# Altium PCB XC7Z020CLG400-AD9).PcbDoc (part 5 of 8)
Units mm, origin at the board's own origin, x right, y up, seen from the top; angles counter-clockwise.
Board outline 38 x 38 mm, 14 copper layers (Top Layer, GND02, ART03, PWR04, ART05, GND06, ART07, ART08, PWR09, ART10, GND11, ART12, PWR13, Bottom Layer); 276 components, 302 nets, 1684 pads, 1576 vias.
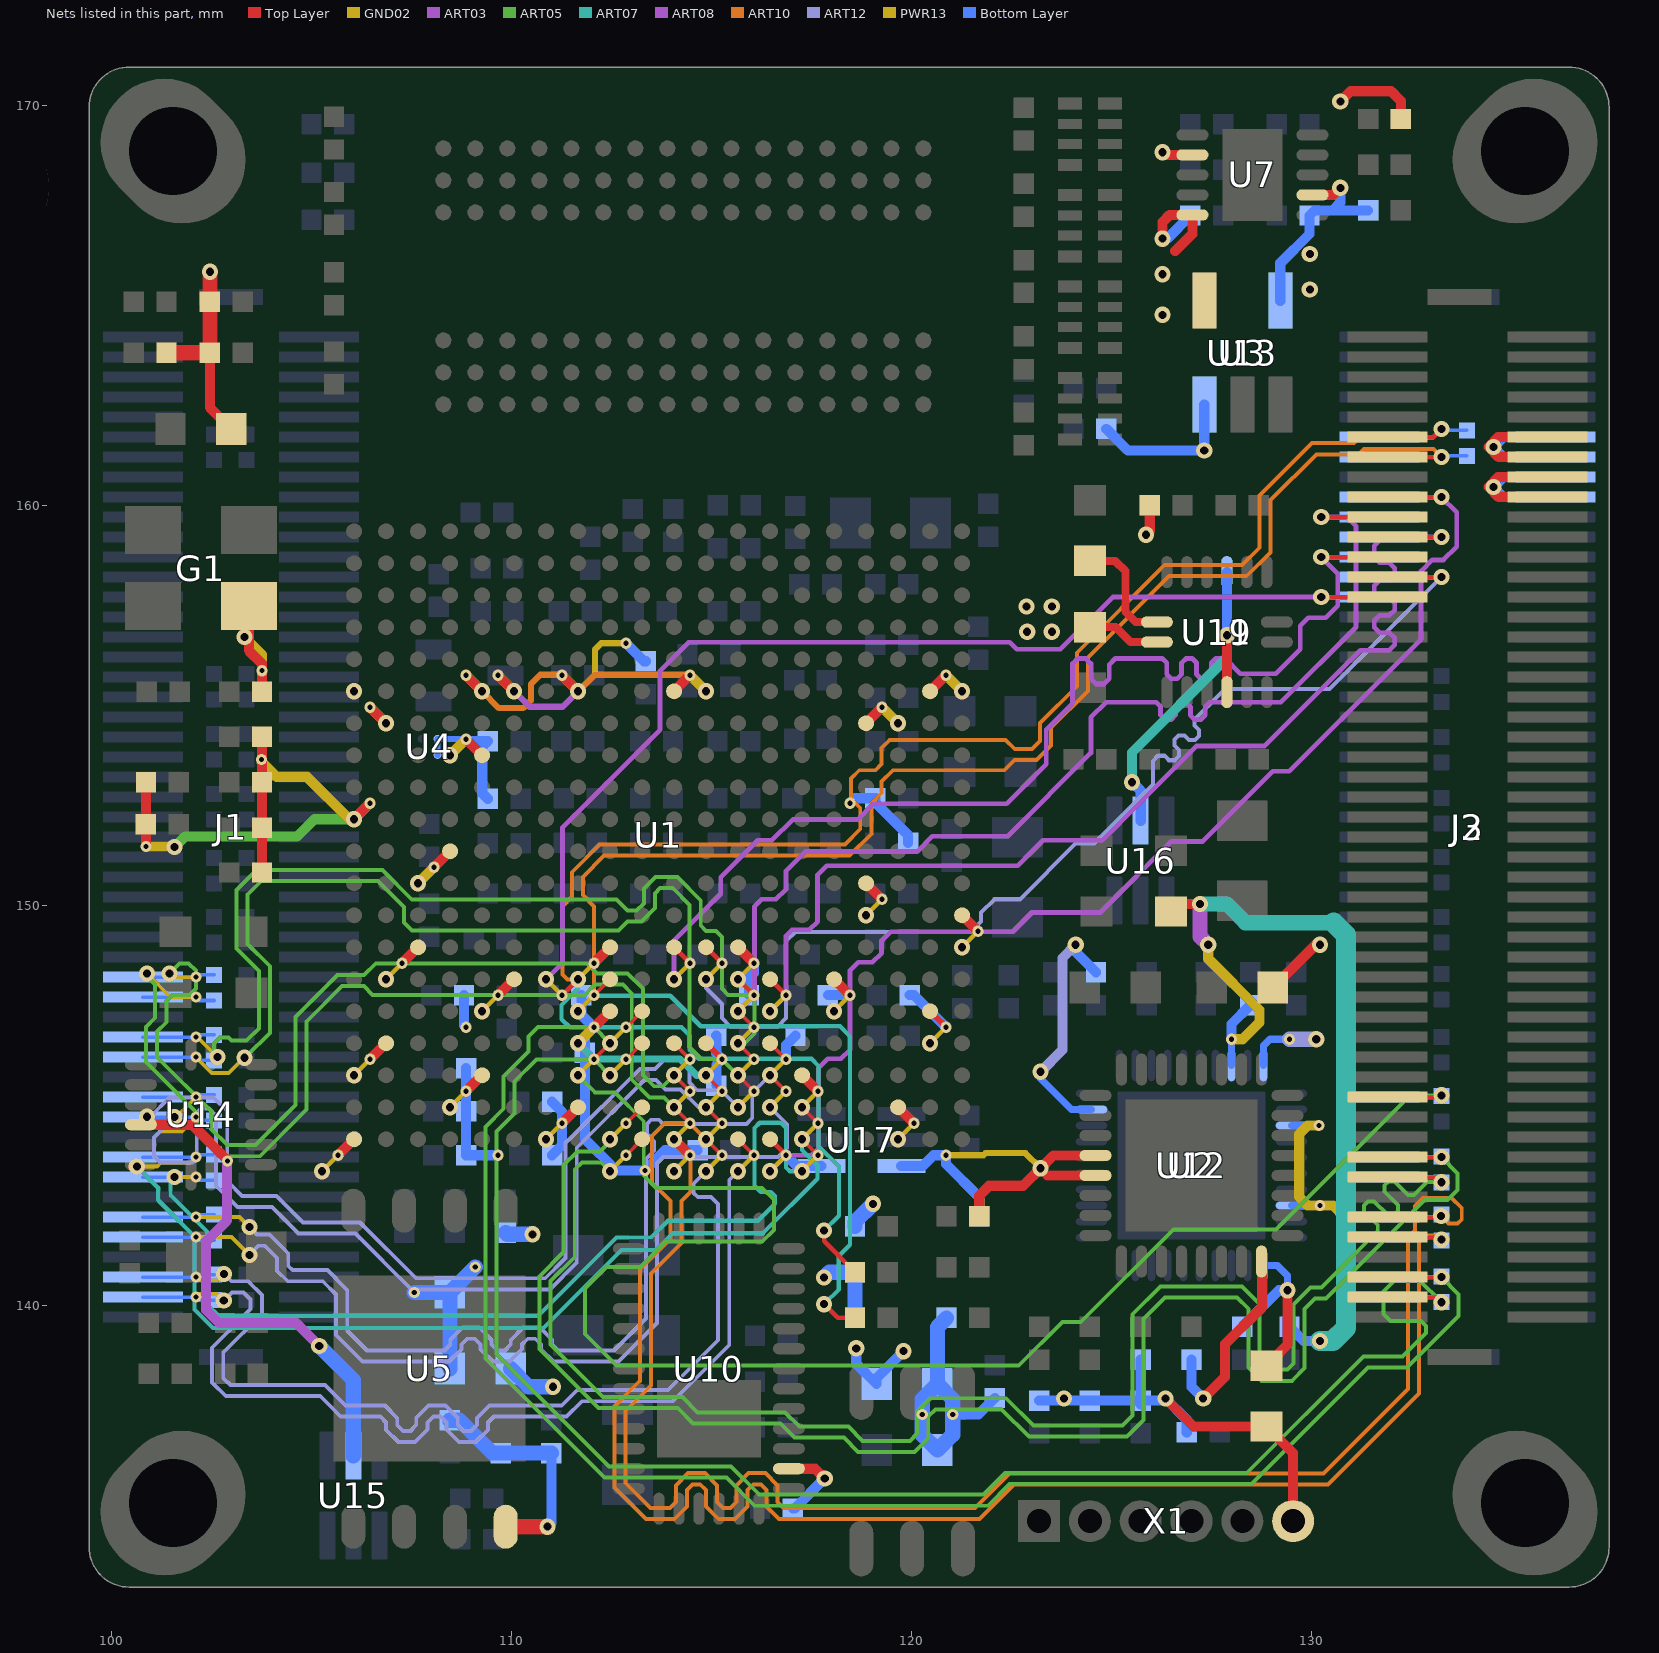
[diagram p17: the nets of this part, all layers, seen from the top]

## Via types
v1: diameter 0.406, hole 0.203, GND02 to PWR13, 466 vias
v2: diameter 0.279, hole 0.127, Top Layer to GND02, tented top, 373 vias
v3: diameter 0.406, hole 0.203, Top Layer to Bottom Layer, 324 vias
v4: diameter 0.279, hole 0.127, PWR13 to Bottom Layer, 207 vias
v5: diameter 0.279, hole 0.127, Top Layer to ART03, tented top, 41 vias
v6: diameter 0.279, hole 0.127, Top Layer to ART03, 40 vias
v7: diameter 0.279, hole 0.127, PWR13 to Bottom Layer, tented bottom, 39 vias
v8: diameter 0.279, hole 0.127, ART12 to Bottom Layer, 30 vias
v9: diameter 0.279, hole 0.127, Top Layer to GND02, 20 vias
v10: diameter 0.406, hole 0.203, Top Layer to Bottom Layer, tented both sides, 16 vias
v11: diameter 0.406, hole 0.203, ART03 to ART12, 11 vias
v12: diameter 0.406, hole 0.203, Top Layer to Bottom Layer, tented top, 9 vias

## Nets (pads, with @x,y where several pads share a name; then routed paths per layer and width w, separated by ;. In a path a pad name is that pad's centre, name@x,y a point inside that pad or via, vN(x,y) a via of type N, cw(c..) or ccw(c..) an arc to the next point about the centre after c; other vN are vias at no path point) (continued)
B35_L8_P: J2.62 J3.62 R114.2 U1.M17 | length 42.8
  Top Layer w0.089: v2(112.065,146.165) U1.M17@112.465,146.565 ; J3.62@131.9,145.219 133.205,145.219 v3(133.248,145.263)
  ART05 w0.099: v1(111.665,145.765) 112.094,145.336 112.586,145.336 113.307,144.615 113.307,143.259 113.614,142.951 116.266,142.951 116.558,142.659 116.558,141.897 116.269,141.608 113.856,141.608 113.221,140.973 112.372,140.973 111.836,140.437 111.836,139.294 112.624,138.506 122.682,138.506 123.772,139.596 124.231,139.596 126.545,141.91 129.108,141.91 132.461,145.263 v3(133.248,145.263)
  GND02 w0.109: v1(111.665,145.765) v2(112.065,146.165)
  Bottom Layer w0.114: J2.62@131.7,145.219 133.23,145.219 133.248,145.237 v3(133.248,145.263)
B35_L9_N: J2.58 J3.58 R117.1 U1.L20 | length 43.9
  Top Layer w0.089: v2(112.865,143.765) U1.L20@113.265,144.165 ; J3.58@131.9,143.219 133.121,143.219 v3(133.248,143.092)
  ART05 w0.099: v1(112.465,143.365) 112.244,143.586 111.76,143.586 111.582,143.408 111.582,141.228 110.973,140.618 110.973,139.04 112.293,137.719 114.271,137.719 114.652,137.338 116.84,137.338 117.196,136.982 118.425,136.982 118.781,136.627 119.964,136.627 120.142,136.804 120.142,137.352 120.481,137.691 122.365,137.691 123.048,137.008 125.273,137.008 125.527,137.262 125.527,139.79 126.221,140.485 128.258,140.485 128.699,140.043 128.699,138.574 128.868,138.405 129.399,138.405 129.553,138.558 129.553,140.039 129.973,140.459 130.252,140.459 130.252,140.463 131.657,141.868 131.657,142.019 131.317,142.358 131.317,142.509 131.417,142.61 131.568,142.61 131.908,142.27 132.059,142.27 132.16,142.371 132.16,142.521 131.82,142.861 131.82,143.012 131.92,143.113 132.071,143.113 132.411,142.773 132.562,142.773 132.566,142.773 132.885,143.092 v3(133.248,143.092)
  GND02 w0.109: v1(112.465,143.365) v2(112.865,143.765)
  Bottom Layer w0.114: J2.58@131.7,143.219 133.121,143.219 v3(133.248,143.092)
B35_L9_P: J2.59 J3.59 R117.2 U1.L19 | length 43.9
  Top Layer w0.089: v2(112.865,144.565) U1.L19@113.265,144.965 ; J3.59@131.9,143.719 v3(133.248,143.719)
  ART05 w0.099: v1(112.465,144.165) 112.465,144.113 112.215,143.863 111.645,143.863 111.305,143.523 111.305,141.342 110.696,140.733 110.696,138.925 112.179,137.442 114.156,137.442 114.537,137.061 116.725,137.061 117.081,136.705 118.311,136.705 118.666,136.35 120.079,136.35 120.419,136.69 120.419,137.237 120.596,137.414 122.25,137.414 122.933,136.731 125.387,136.731 125.804,137.147 125.804,139.676 126.336,140.208 128.143,140.208 128.422,139.929 128.422,138.459 128.754,138.128 129.514,138.128 129.829,138.444 129.829,139.925 130.088,140.183 130.367,140.183 132.831,142.646 133.401,142.646 133.655,142.9 133.655,143.313 v3(133.248,143.719)
  GND02 w0.109: v1(112.465,144.165) v2(112.865,144.565)
  Bottom Layer w0.114: J2.59@131.7,143.719 v3(133.248,143.719)
B35_L10_N: J2.55 J3.55 R120.1 U1.J19 | length 43.8
  Top Layer w0.089: U1.J19@114.865,144.965 v2(115.265,144.565) ; J3.55@131.9,141.719 133.185,141.719 v3(133.248,141.656)
  ART10 w0.099: v1(114.865,144.165) 114.453,144.577 113.843,144.577 113.513,144.247 113.513,143.078 113.971,142.62 113.971,141.682 113.21,140.922 113.21,138.128 112.572,137.489 112.572,135.459 113.36,134.671 114.077,134.671 114.385,134.979 114.385,135.394 114.531,135.54 114.719,135.54 114.865,135.394 114.865,134.979 115.173,134.671 115.591,134.671 115.899,134.979 115.899,135.394 116.045,135.54 116.233,135.54 116.379,135.394 116.379,134.979 116.687,134.671 121.702,134.671 122.566,135.534 126.797,135.534 130.414,135.534 132.69,137.81 132.69,141.591 132.856,141.757 133.147,141.757 v3(133.248,141.656)
  GND02 w0.109: v1(114.865,144.165) v2(115.265,144.565)
  Bottom Layer w0.114: J2.55@131.7,141.719 R120.1@133.185,141.719
B35_L10_P: J2.56 J3.56 R120.2 U1.K19 | length 43.8
  Top Layer w0.089: U1.K19@114.065,144.965 v2(114.465,144.565) ; J3.56@131.9,142.219 133.215,142.219 v3(133.243,142.247)
  ART10 w0.099: v1(114.065,144.165) 114.478,143.752 114.478,142.85 114.248,142.62 114.248,141.568 113.487,140.807 113.487,138.013 112.849,137.375 112.849,135.574 113.475,134.948 113.962,134.948 114.108,135.094 114.108,135.508 114.416,135.816 114.834,135.816 115.142,135.508 115.142,135.094 115.288,134.948 115.476,134.948 115.622,135.094 115.622,135.508 115.93,135.816 116.348,135.816 116.656,135.508 116.656,135.094 116.802,134.948 121.587,134.948 122.451,135.811 130.299,135.811 132.413,137.925 132.413,141.706 132.588,141.881 132.588,142.494 132.791,142.697 133.502,142.697 133.756,142.443 133.756,142.164 133.655,142.062 133.427,142.062 v3(133.243,142.247)
  GND02 w0.109: v1(114.065,144.165) v2(114.465,144.565)
  Bottom Layer w0.114: J2.56@131.7,142.219 R120.2@133.215,142.219
B35_L11_N: J2.52 J3.52 R123.1 U1.L17 | length 43.8
  Top Layer w0.089: v2(112.865,146.165) U1.L17@113.265,146.565 ; J3.52@131.9,140.219 133.121,140.219 v3(133.248,140.092)
  ART05 w0.099: v1(112.465,145.765) 112.071,146.159 110.624,146.159 110.081,145.616 110.081,144.814 109.626,144.359 109.626,138.8 112.437,135.989 115.485,135.989 116.194,135.28 121.797,135.28 122.337,135.821 128.382,135.821 131.296,138.735 132.273,138.735 132.862,139.324 132.862,139.502 132.74,139.624 131.978,139.624 131.801,139.802 131.801,140.36 132.08,140.64 132.701,140.64 v3(133.248,140.092)
  GND02 w0.109: v1(112.465,145.765) v2(112.865,146.165)
  Bottom Layer w0.114: J2.52@131.7,140.219 R123.1@133.121,140.219
B35_L11_P: J2.53 J3.53 R123.2 U1.L16 | length 43.8
  Top Layer w0.089: v2(112.865,146.965) U1.L16@113.265,147.365 ; J3.53@131.9,140.719 v3(133.248,140.719)
  ART05 w0.099: v1(112.465,146.565) 112.059,146.971 110.668,146.971 110.428,146.732 110.428,146.354 109.804,145.73 109.804,144.929 109.35,144.474 109.35,138.685 112.322,135.712 115.37,135.712 116.079,135.004 121.911,135.004 122.452,135.544 128.497,135.544 131.411,138.458 132.387,138.458 133.68,139.751 133.68,140.287 v3(133.248,140.719)
  GND02 w0.109: v1(112.465,146.565) v2(112.865,146.965)
  Bottom Layer w0.114: J2.53@131.7,140.719 v3(133.248,140.719)
B35_L12_N: J1.34 R104.2 U1.K18 | length 27
  Top Layer w0.089: U1.K18@114.065,145.765 v2(114.465,145.365)
  ART05 w0.099: v1(100.889,148.311) 100.889,148.234 101.092,148.031 101.092,147.204 100.863,146.975 100.863,146.101 102.212,144.752 102.212,144.31 102.781,143.741 103.711,143.741 104.874,144.904 104.874,147.104 105.763,147.993 106.312,147.993 106.528,147.777 111.836,147.777 112.091,148.032 112.79,148.032 113.007,147.815 113.007,145.656 113.449,145.214 113.816,145.214 v1(114.065,144.965)
  GND02 w0.109: v1(114.065,144.965) v2(114.465,145.365)
  PWR13 w0.089: v1(100.889,148.311) 101.48,147.719 v4(102.111,147.719)
  Bottom Layer w0.089: J1.34@100.782,147.719 v4(102.111,147.719) 102.195,147.635 R104.2@102.565,147.635
B35_L12_P: J1.33 R104.1 U1.K17 | length 27
  Top Layer w0.089: U1.K17@114.065,146.565 v2(114.465,146.165)
  ART05 w0.099: v1(101.448,148.311) 101.702,148.565 101.93,148.565 102.108,148.387 102.108,147.93 101.956,147.777 101.524,147.777 101.371,147.625 101.371,147.091 101.14,146.86 101.14,146.215 102.489,144.867 102.489,144.424 102.895,144.018 103.596,144.018 104.597,145.019 104.597,147.218 105.649,148.27 106.312,148.27 106.606,148.565 111.887,148.565 112.142,148.309 112.904,148.309 113.284,147.93 113.284,145.771 113.563,145.491 113.791,145.491 v1(114.065,145.765)
  GND02 w0.109: v1(114.065,145.765) v2(114.465,146.165)
  PWR13 w0.089: v1@101.539,148.219 v4(102.111,148.219)
  Bottom Layer w0.089: J1.33@100.782,148.219 v4(102.111,148.219) ; v4@102.167,148.275 R104.1@102.565,148.275
B35_L13_N: J1.37 R109.2 U1.H17 | length 26.9
  Top Layer w0.089: U1.H17@115.665,146.565 v2(116.065,146.165)
  ART05 w0.099: v1(103.327,146.202) 103.327,146.22 103.337,146.23 103.38,146.23 103.38,146.244 103.96,146.824 103.96,148.491 103.401,149.05 103.401,150.279 103.744,150.622 106.658,150.622 107.311,149.969 107.311,149.912 107.311,149.588 107.518,149.381 112.678,149.381 112.904,149.607 113.245,149.607 113.586,149.949 113.586,150.315 113.716,150.444 114.032,150.444 114.455,150.021 114.455,146.474 114.752,146.177 115.253,146.177 v1(115.665,145.765)
  GND02 w0.109: v1(115.665,145.765) v2(116.065,146.165)
  PWR13 w0.089: v4(102.111,146.219) 102.509,145.821 102.929,145.821 v1@103.327,146.22 ; v1(103.327,146.202) v1@103.327,146.22 ; v1@103.337,146.23 v1@103.327,146.22
  Bottom Layer w0.089: J1.37@100.782,146.219 v4(102.111,146.219) 102.194,146.136 R109.2@102.565,146.136
B35_L13_P: J1.36 R109.1 U1.H16 | length 26.9
  Top Layer w0.089: U1.H16@115.665,147.365 v2(116.065,146.965)
  ART05 w0.099: v1(102.649,146.219) 102.565,146.303 102.565,146.558 102.718,146.71 102.921,146.71 102.997,146.634 103.378,146.634 103.683,146.939 103.683,148.376 103.124,148.935 103.124,150.393 103.629,150.899 106.773,150.899 107.507,150.165 112.624,150.165 112.904,149.884 113.13,149.884 113.309,150.063 113.309,150.429 113.601,150.721 114.147,150.721 114.732,150.136 114.732,149.504 114.861,149.375 115.115,149.375 115.265,149.225 115.265,147.93 115.418,147.777 115.951,147.777 116.078,147.65 116.078,146.812 115.831,146.565 v1(115.665,146.565)
  GND02 w0.109: v1(115.665,146.565) v2(116.065,146.965)
  PWR13 w0.089: v4@102.149,146.719 v1(102.649,146.219)
  Bottom Layer w0.089: J1.36@100.782,146.719 v4(102.111,146.719) 102.168,146.776 R109.1@102.565,146.776
B35_L14_N: J1.40 R112.2 U1.H18 | length 27
  Top Layer w0.089: U1.H18@115.665,145.765 v2(116.065,145.365)
  ART12 w0.097: v1(100.885,144.73) 100.969,144.73 101.452,145.212 102.554,145.212 102.895,144.87 102.895,143.118 103.265,142.748 104.129,142.748 104.789,142.088 106.212,142.088 107.609,140.691 110.846,140.691 111.354,141.199 111.354,144.069 113.208,145.923 113.589,145.923 113.817,146.152 114.198,146.152 114.452,145.898 114.452,145.582 114.644,145.39 115.24,145.39 v1(115.665,144.965)
  GND02 w0.109: v1(115.665,144.965) v2(116.065,145.365)
  PWR13 w0.089: v1(100.885,144.73) 101.266,144.348 101.74,144.348 v4(102.111,144.719)
  Bottom Layer w0.089: J1.40@100.782,144.719 v4(102.111,144.719) 102.192,144.638 R112.2@102.565,144.638
B35_L14_P: J1.39 R112.1 U1.J18 | length 27
  Top Layer w0.089: U1.J18@114.865,145.765 v2(115.265,145.365)
  ART12 w0.097: v1(101.573,144.719) 101.067,144.213 101.067,143.739 101.219,143.586 102.032,143.586 102.133,143.688 102.133,144.831 102.235,144.932 102.438,144.932 102.616,144.755 102.616,143.002 103.149,142.469 104.013,142.469 104.673,141.808 106.096,141.808 107.493,140.411 110.961,140.411 111.633,141.083 111.633,143.953 113.324,145.644 113.614,145.644 113.846,145.412 114.227,145.412 114.674,144.965 v1(114.865,144.965)
  GND02 w0.109: v1(114.865,144.965) v2(115.265,145.365)
  PWR13 w0.089: v1(101.573,144.719) 101.611,144.719 v4(102.111,145.219)
  Bottom Layer w0.089: J1.39@100.782,145.219 v4(102.111,145.219) 102.17,145.278 R112.1@102.565,145.278
B35_L15_N: J1.43 R115.2 U1.F20 | length 27.1
  Top Layer w0.089: U1.F20@117.265,144.165 v2(117.665,143.765)
  GND02 w0.109: v1(117.265,143.365) v2(117.665,143.765)
  ART07 w0.107: v1@101.571,143.219 v1(101.573,143.219) 101.478,143.124 101.478,142.768 102.387,141.859 102.387,140.037 102.668,139.756 110.673,139.756 112.624,141.707 113.487,141.707 113.91,142.129 116.164,142.129 116.586,142.551 116.586,142.748 116.484,142.85 116.23,142.85 116.078,143.002 116.078,144.45 116.205,144.577 116.738,144.577 116.865,144.45 116.865,143.459 116.96,143.365 v1(117.265,143.365)
  PWR13 w0.102: v1(101.573,143.219) v4(102.111,143.219)
  Bottom Layer w0.089: J1.43@100.782,143.219 v4(102.111,143.219) 102.191,143.139 R115.2@102.565,143.139
B35_L15_P: J1.42 R115.1 U1.F19 | length 27.2
  Top Layer w0.089: U1.F19@117.265,144.965 v2(117.665,144.565)
  GND02 w0.109: v1(117.265,144.165) v2(117.665,144.565)
  ART07 w0.107: v1@100.635,143.48 v1(100.635,143.485) 101.168,142.951 101.168,142.64 102.078,141.731 102.078,139.908 102.54,139.446 110.801,139.446 112.752,141.397 113.616,141.397 114.038,141.819 116.292,141.819 117.653,143.18 117.653,143.51 117.265,143.898 v1(117.265,144.165)
  PWR13 w0.089: v1(100.635,143.485) 101.14,143.485 101.234,143.578 101.97,143.578 v4(102.111,143.719)
  Bottom Layer w0.089: J1.42@100.782,143.719 v4(102.111,143.719) 102.171,143.779 R115.1@102.565,143.779
B35_L16_N: J1.46 R118.2 U1.G18 | length 27
  Top Layer w0.089: U1.G18@116.465,145.765 v2(116.865,145.365)
  ART12 w0.097: v1(103.447,141.275) 103.676,141.503 103.835,141.503 104.14,141.199 104.14,140.88 104.405,140.614 105.283,140.614 105.613,140.284 105.613,139.268 106.274,138.608 108.439,138.608 108.748,138.917 108.748,139.034 108.893,139.179 109.08,139.179 109.225,139.034 109.225,138.917 109.534,138.608 109.952,138.608 110.261,138.917 110.261,139.034 110.407,139.179 110.594,139.179 110.739,139.034 110.739,138.917 111.048,138.608 112.674,138.608 113.64,139.573 113.64,143.561 113.797,143.718 116.667,143.718 116.891,143.942 116.891,144.539 v1(116.465,144.965)
  GND02 w0.109: v1(116.465,144.965) v2(116.865,145.365)
  PWR13 w0.102: v4(102.111,141.719) 103.003,141.719 v1(103.447,141.275)
  Bottom Layer w0.089: J1.46@100.782,141.719 v4(102.111,141.719) 102.19,141.641 R118.2@102.565,141.641
B35_L16_P: J1.45 R118.1 U1.G17 | length 27
  Top Layer w0.089: U1.G17@116.465,146.565 v2(116.865,146.165)
  ART12 w0.097: v1(103.447,141.974) 103.638,141.783 103.951,141.783 104.419,141.314 104.419,140.995 104.521,140.894 105.399,140.894 105.893,140.4 105.893,139.384 106.389,138.887 108.323,138.887 108.468,139.032 108.468,139.15 108.777,139.459 109.196,139.459 109.504,139.15 109.504,139.032 109.65,138.887 109.837,138.887 109.982,139.032 109.982,139.15 110.291,139.459 110.709,139.459 111.018,139.15 111.018,139.032 111.164,138.887 112.559,138.887 113.36,139.689 113.36,143.677 113.569,143.885 113.569,144.114 113.386,144.297 113.386,144.551 113.487,144.653 113.69,144.653 113.792,144.551 115.875,144.551 116.018,144.695 116.018,145.318 v1(116.465,145.765)
  GND02 w0.109: v1(116.465,145.765) v2(116.865,146.165)
  PWR13 w0.102: v4(102.111,142.219) 103.202,142.219 v1(103.447,141.974)
  Bottom Layer w0.089: J1.45@100.782,142.219 v4(102.111,142.219) 102.172,142.281 R118.1@102.565,142.281
B35_L17_N: J1.49 R121.2 U1.H20 | length 27
  Top Layer w0.089: U1.H20@115.665,144.165 v2(116.065,143.765)
  ART12 w0.097: v1(102.806,140.132) 103.009,140.335 103.302,140.335 103.48,140.157 103.48,139.917 102.514,138.952 102.514,138.086 102.856,137.744 105.218,137.744 105.732,137.231 106.718,137.231 106.863,137.085 106.863,136.904 107.172,136.596 107.591,136.596 107.9,136.904 107.9,137.085 108.045,137.231 108.232,137.231 108.377,137.085 108.377,136.904 108.686,136.596 109.105,136.596 109.414,136.904 109.414,137.085 109.559,137.231 111.006,137.231 111.373,137.231 111.76,137.617 114.035,137.617 115.443,139.025 115.443,143.143 v1(115.665,143.365)
  GND02 w0.109: v1(115.665,143.365) v2(116.065,143.765)
  PWR13 w0.089: v4(102.111,140.219) 102.19,140.298 102.64,140.298 v1(102.806,140.132)
  Bottom Layer w0.089: J1.49@100.782,140.219 v4(102.111,140.219) 102.188,140.142 R121.2@102.565,140.142
B35_L17_P: J1.48 R121.1 U1.J20 | length 27
  Top Layer w0.089: U1.J20@114.865,144.165 v2(115.265,143.765)
  ART12 w0.097: v1(102.812,140.799) 102.997,140.614 103.418,140.614 103.759,140.273 103.759,139.802 102.794,138.836 102.794,138.201 102.972,138.024 105.334,138.024 105.847,137.51 106.834,137.51 107.143,137.201 107.143,137.02 107.288,136.875 107.475,136.875 107.62,137.02 107.62,137.201 107.929,137.51 108.348,137.51 108.657,137.201 108.657,137.02 108.802,136.875 108.989,136.875 109.134,137.02 109.134,137.201 109.443,137.51 110.89,137.51 111.258,137.51 111.644,137.897 113.919,137.897 115.164,139.141 115.164,142.545 114.986,142.723 114.656,142.723 114.554,142.824 114.554,143.054 v1(114.865,143.365)
  GND02 w0.109: v1(114.865,143.365) v2(115.265,143.765)
  PWR13 w0.089: v4(102.111,140.719) 102.19,140.641 102.654,140.641 v1(102.812,140.799)
  Bottom Layer w0.089: J1.48@100.782,140.719 v4(102.111,140.719) 102.174,140.782 R121.1@102.565,140.782
B35_S0: J2.92 J3.92 U1.G20 | length 32.6
  Top Layer w0.114: U1.G20@116.465,144.165 v2(116.865,143.765) ; J3.92@131.9,160.219 v3(133.248,160.219)
  GND02 w0.109: v1(116.465,143.365) v2(116.865,143.765)
  ART08 w0.119: v1(116.465,143.365) 116.865,143.765 117.5,143.765 117.678,143.943 117.678,145.948 117.907,146.177 118.237,146.177 118.466,146.406 118.466,148.387 118.669,148.59 119.024,148.59 119.253,148.819 119.253,149.123 119.482,149.352 122.53,149.352 123.012,149.835 124.714,149.835 126.492,151.613 127.279,151.613 129.032,153.365 129.438,153.365 132.74,156.667 132.74,158.369 133.02,158.648 133.299,158.648 133.629,158.979 133.629,159.838 v3(133.248,160.219)
  Bottom Layer w0.114: J2.92@131.7,160.219 v3(133.248,160.219)
B35_S1: J2.91 J3.91 U1.H15 | length 30.5
  Top Layer w0.114: U1.H15@115.665,148.165 v2(116.065,147.765) ; v3(130.243,159.719) J3.91@131.9,159.719
  GND02 w0.109: v1(115.665,147.365) v2(116.065,147.765)
  ART08 w0.119: v1(115.665,147.365) 116.078,147.778 116.078,149.987 116.256,150.165 116.611,150.165 116.865,150.419 116.865,150.876 117.348,151.359 120.142,151.359 120.523,151.74 122.403,151.74 124.485,153.822 124.485,154.711 124.866,155.092 126.115,155.092 126.227,154.98 126.227,154.763 126.339,154.651 126.488,154.651 126.6,154.763 126.6,154.98 126.712,155.092 126.861,155.092 126.973,154.98 126.973,154.763 127.085,154.651 127.235,154.651 127.347,154.763 127.347,154.98 127.459,155.092 129.235,155.092 131.115,156.972 131.115,159.487 130.882,159.719 v3(130.243,159.719)
  Bottom Layer w0.114: v3(130.243,159.719) J2.91@131.7,159.719
B35_S2: J2.90 J3.90 U1.G15 | length 31
  Top Layer w0.114: U1.G15@116.465,148.165 v2(116.865,147.765) ; J3.90@131.9,159.219 v3(133.248,159.219)
  GND02 w0.109: v1(116.465,147.365) v2(116.865,147.765)
  ART08 w0.119: v1(116.465,147.365) v2(116.865,147.765) 116.865,149.25 117.016,149.401 117.447,149.401 117.653,149.606 117.653,150.774 117.881,151.003 122.657,151.003 123.292,151.638 124.765,151.638 127.127,154 128.829,154 131.22,156.392 131.949,156.392 132.08,156.523 132.08,156.698 131.949,156.829 131.703,156.829 131.572,156.96 131.572,157.135 131.703,157.266 131.949,157.266 132.08,157.397 132.08,157.571 131.949,157.703 131.703,157.703 131.572,157.834 131.572,158.008 131.703,158.139 131.949,158.139 132.08,158.27 132.08,158.445 131.949,158.576 131.703,158.576 131.572,158.707 131.572,159.004 131.787,159.219 v3(133.248,159.219)
  Bottom Layer w0.114: J2.90@131.7,159.219 v3(133.248,159.219)
B35_S3: J2.89 J3.89 U1.K14 | length 31.1
  Top Layer w0.114: U1.K14@114.065,148.965 v2(114.465,148.565) ; v3(130.243,158.719) J3.89@131.9,158.719
  GND02 w0.109: v1(114.065,148.165) v2(114.465,148.565)
  ART08 w0.119: v1(114.065,148.165) 114.065,149.142 115.229,150.306 115.229,150.413 ; 115.229,150.413 115.229,150.713 116.154,151.638 116.51,151.638 117.03,152.159 118.656,152.159 119.05,152.552 122.377,152.552 123.368,153.543 123.368,154.407 124.028,155.067 124.028,156.058 124.155,156.185 124.358,156.185 124.485,156.058 124.485,155.677 124.612,155.55 124.816,155.55 124.943,155.677 124.943,156.032 125.095,156.185 126.267,156.185 126.379,156.073 126.379,155.789 126.491,155.677 126.64,155.677 126.752,155.789 126.752,156.073 126.864,156.185 127.014,156.185 127.126,156.073 127.126,155.789 127.238,155.677 127.387,155.677 127.499,155.789 127.499,156.073 127.611,156.185 127.838,156.185 128.219,155.804 129.108,155.804 129.718,156.413 129.718,156.997 129.921,157.201 130.353,157.201 130.658,157.505 130.658,158.305 v3(130.243,158.719)
  Bottom Layer w0.114: v3(130.243,158.719) J2.89@131.7,158.719
B35_S4: J2.88 J3.88 U1.J14 | length 30.5
  Top Layer w0.114: U1.J14@114.865,148.965 v2(115.265,148.565) ; J3.88@131.9,158.219 v3(133.248,158.219)
  ART12 w0.102: v1(114.865,148.165) 114.865,147.949 115.265,147.549 115.265,147.193 115.468,146.99 116.662,146.99 116.865,147.193 116.865,149.123 117.094,149.352 121.488,149.352 121.742,149.606 121.742,149.835 122.072,150.165 122.708,150.165 124.105,151.562 124.562,151.562 126.035,153.035 126.035,153.619 126.169,153.754 126.32,153.754 126.432,153.641 126.583,153.641 126.684,153.742 126.684,153.893 126.572,154.005 126.572,154.156 126.672,154.256 126.823,154.256 126.935,154.144 127.086,154.144 127.187,154.245 127.187,154.396 127.074,154.508 127.074,154.659 127.838,155.423 130.452,155.423 v3(133.248,158.219)
  GND02 w0.109: v1(114.865,148.165) v2(115.265,148.565)
  Bottom Layer w0.114: J2.88@131.7,158.219 v3(133.248,158.219)
B35_S5: J2.87 J3.87 U1.N15 | length 30.6
  Top Layer w0.114: v2(111.265,147.765) U1.N15@111.665,148.165 ; v3(130.243,157.719) J3.87@131.9,157.719
  GND02 w0.109: v1(110.865,148.165) v2(111.265,147.765)
  ART08 w0.119: v1(110.865,148.165) 111.277,148.577 111.277,151.968 113.716,154.407 113.716,155.88 114.427,156.591 122.453,156.591 122.631,156.413 123.723,156.413 125.029,157.719 v3(130.243,157.719)
  Bottom Layer w0.114: v3(130.243,157.719) J2.87@131.7,157.719
BANK13_VCC: C8.1 C9.1 C24.2 C30.1 C31.1 C32.1 C36.2 C37.1 C38.1 C46.1 C48.1 C77.1 C78.1 C93.1 C94.1 C144.2 C147.1 C148.1 C254.1 F4.1 F5.1 F8.1 G1.4 R13.1 R14.1 R23.1 R31.1 R32.1 R33.1 R34.1 R35.2 R36.1 R37.2 R40.2 R58.1 R60.1 R65.1 R136.2 R144.2 U1.B6 U1.D7 U1.K6 U1.N6 U1.R6 U1.T6 U1.T8 U1.U11 U1.W7 U1.Y10 U2.29 U2.40 U3.5 U4.A2 U4.B2 U5.8 U7.2 U7.7 U7.10 U12.20 U12.21 U13.3 U13.5 U17.6 U19.7 U19.8 X1.6 | length 109.8
  Top Layer w0.203: C78.1@124.46,156.97 125.097,156.97 125.472,156.595 U19.8@126.135,156.595 ; C77.1@124.46,158.625 125.093,158.625 125.349,158.369 125.349,157.353 125.607,157.095 U19.7@126.135,157.095
  Top Layer w0.254: C9.1@100.86,152.044 100.86,151.489 v2(100.863,151.486) ; C9.1@100.863,152.044 C30.1@100.863,153.086 ; R37.2@102.46,163.83 102.46,162.46 C38.1@102.995,161.925 ; G1.4@103.435,157.495 103.435,156.382 103.763,156.054 v2(103.763,155.88) C46.1@103.763,155.353 ; v2(103.752,153.663) v2@103.763,153.674 ; C37.1@103.763,150.835 C148.1@103.763,151.954 C32.1@103.763,153.086 v2@103.763,153.674 ; C8.1@103.763,154.229 v2@103.763,153.674 ; v1(106.065,152.165) v2(106.465,152.565) ; v2(106.465,154.965) v1(106.865,154.565) ; v2(108.065,150.965) U1.U11@108.465,151.365 ; v4(108.865,154.165) U1.T8@109.265,153.765 ; v2(108.865,155.765) v1(109.265,155.365) ; v2(109.665,155.765) v1(110.065,155.365) ; v2(111.265,155.765) v1(111.665,155.365) ; U1.K6@114.065,155.365 v2(114.465,155.765) ; U1.D7@118.865,154.565 v2(119.265,154.965) ; U1.B6@120.465,155.365 v2(120.865,155.765) ; C254.1@121.695,142.24 121.695,142.752 121.945,143.002 122.79,143.002 v3(123.228,143.44) 123.548,143.76 U12.20@124.6,143.76 ; 123.408,143.26 U12.21@124.6,143.26 ; v3(125.864,159.278) 125.955,159.369 R23.1@125.955,160.02 ; v3(126.276,166.681) 126.276,167.094 126.457,167.275 U7.10@127.024,167.275 127.024,166.8 126.594,166.37 ; v3(126.276,168.84) 126.341,168.775 U7.7@127.024,168.775 ; v3(126.352,137.684) 127.052,136.984 F8.1@128.88,136.984 129.54,136.324 X1.6@129.54,134.62 ; U7.2@130.024,167.775 130.545,167.775 v3(130.721,167.951) ; v3(130.721,170.11) 130.975,170.364 131.991,170.364 132.236,170.119 R65.1@132.236,169.672
  Top Layer w0.381: R35.2@101.375,163.83 R37.2@102.46,163.83 R36.1@102.46,165.1 v3(102.46,165.852) ; U5.8@109.855,134.48 v3(110.9,134.48)
  ART03 w0.152: v1(110.065,155.365) 110.453,154.977 111.277,154.977 v1(111.665,155.365)
  ART05 w0.254: v1(101.573,151.469) 101.835,151.731 104.639,151.731 105.073,152.165 v1(106.065,152.165)
  ART10 w0.152: v1(109.265,155.365) 109.684,154.946 110.293,154.946 110.484,155.137 110.484,155.544 110.719,155.778 111.252,155.778 v1(111.665,155.365) 112.078,155.778 114.452,155.778 v1(114.865,155.365)
  ART12 w0.254: v3(123.228,145.853) 123.774,146.399 123.774,148.698 v3(124.104,149.028)
  ART12 w0.381: v8(129.451,146.666) v11(130.118,146.666)
  GND02 w0.254: v2(100.863,151.486) v1@101.573,151.486 ; v1(103.327,156.719) 103.763,156.284 v2(103.763,155.88) ; v2(103.752,153.663) 103.752,153.601 104.123,153.23 104.885,153.23 105.95,152.165 v1(106.065,152.165) v2(106.465,152.565) ; v2(106.465,154.965) v1(106.865,154.565) ; v1(107.665,150.565) v2(108.065,150.965) ; v1(108.465,153.765) v4(108.865,154.165) ; v2(108.865,155.765) v1(109.265,155.365) ; v2(109.665,155.765) v1(110.065,155.365) ; v2(111.265,155.765) v1(111.665,155.365) ; v2(114.465,155.765) v1(114.865,155.365) ; v2(119.265,154.965) v1(119.665,154.565) ; v2(120.865,155.765) v1(121.265,155.365)
  PWR13 w0.152: v1(108.465,153.765) v4(108.865,154.165) ; v1(111.665,155.365) 112.084,155.784 112.084,156.407 112.243,156.566 112.394,156.566 ; 112.394,156.565 v4(112.865,156.565) ; v4(120.865,143.765) 121.794,143.765 121.85,143.821 122.847,143.821 v3(123.228,143.44)
  Bottom Layer w0.152: U4.A2@108.15,153.775 U4.B2@108.15,154.175 108.855,154.175 v4(108.865,154.165)
  Bottom Layer w0.178: v3(123.228,145.853) 123.228,145.682 124,144.91 U2.29@124.5,144.91 ; U2.40@128.8,146.01 128.8,146.504 128.962,146.666 v8(129.451,146.666)
  Bottom Layer w0.254: v4(108.865,154.165) 108.911,154.119 C36.2@109.407,154.119 109.271,153.982 109.271,152.814 C31.1@109.407,152.678 ; v3(110.9,134.48) 110.998,134.578 C48.1@110.998,136.32 ; v4(112.865,156.565) 113.314,156.116 R40.2@113.36,156.116 ; v3(118.618,138.938) 118.618,138.557 119.126,138.049 F4.1@119.128,138.049 119.128,138.197 v3(119.799,138.868) ; U17.6@119.745,143.495 120.279,143.495 120.549,143.765 v4(120.865,143.765) 120.865,143.549 121.695,142.719 C144.2@121.695,142.24 ; R31.1@123.19,137.633 123.761,137.633 v3(123.812,137.684) 123.863,137.633 R32.1@124.46,137.633 R33.1@125.73,137.633 ; v3(124.104,149.028) 124.104,148.848 R13.1@124.612,148.34 ; C147.1@124.87,161.925 125.41,161.385 v3(127.32,161.385) U13.3@127.32,162.53 ; R33.1@125.73,137.541 R33.1@125.73,137.633 ; R136.2@125.73,138.655 R33.1@125.73,137.633 ; v3(126.276,166.681) 126.393,166.681 C93.1@126.971,167.259 ; v3@126.301,137.633 R33.1@125.73,137.633 ; v3(126.352,137.684) 126.882,137.154 R34.1@126.882,136.836 ; U13.5@129.22,165.13 129.22,166.069 129.95,166.799 C94.1@129.95,167.259 130.077,167.386 130.524,167.386 ; v3(130.721,167.951) 130.721,167.583 130.524,167.386 ; R14.1@131.416,167.386 130.524,167.386
  Bottom Layer w0.381: R58.1@108.458,137.14 108.7,137.14 109.52,136.32 C24.2@109.728,136.32 C48.1@110.998,136.32 ; R60.1@109.855,141.83 109.896,141.789 v3(110.528,141.789) ; F5.1@109.98,138.43 110.431,137.979 v3(111.036,137.979) ; R144.2@118.589,141.986 118.589,142.103 v3(119.037,142.551)
  other v1: 106.065,155.365
  other v2: 108.865,154.165
  other v3: 122.892,156.852 123.508,156.852 122.873,157.487 123.508,157.487 126.276,164.776 129.959,165.411 126.276,165.792 129.959,166.3
BANK34_VCC: C18.1 C19.1 C20.1 C21.1 C22.1 C23.1 F3.2 F5.2 J2.44 J2.45 J3.44 J3.45 U1.N19 U1.R15 U1.T18 U1.V14 U1.W17 U1.Y20 | length 22.3
  Top Layer w0.254: v2(105.665,143.765) U1.Y20@106.065,144.165 ; v2(106.465,146.165) U1.W17@106.865,146.565 ; v2(107.265,148.565) U1.V14@107.665,148.965 ; v4(108.865,145.365) U1.T18@109.265,145.765 ; v2(109.665,147.765) U1.R15@110.065,148.165 ; v4(111.265,144.565) U1.N19@111.665,144.965 ; J3.44@135.9,161.219 134.678,161.219 134.424,161.473 134.67,161.719 J3.45@135.9,161.719
  GND02 w0.109: v1(105.265,143.365) v2(105.665,143.765) ; v1(106.065,145.765) v2(106.465,146.165) ; v1(106.865,148.165) v2(107.265,148.565) ; v1(108.465,144.965) v4(108.865,145.365) ; v1(109.265,147.365) v2(109.665,147.765) ; v1(110.865,144.165) v4(111.265,144.565)
  Bottom Layer w0.254: C22.1@108.814,147.765 108.814,147.016 v4(108.865,146.965) ; C23.1@108.865,145.943 C19.1@108.865,144.864 C21.1@108.865,143.765 v4(109.665,143.765) ; C20.1@111.015,143.765 111.265,144.015 v4(111.265,144.565) 111.265,144.852 C18.1@111.015,145.102 ; J2.44@136.1,161.219 134.802,161.219 v10(134.548,161.473) 134.794,161.719 J2.45@136.1,161.719
  Bottom Layer w0.381: v4(107.569,140.335) F3.2@108.46,140.335 ; F5.2@108.46,138.43 F3.2@108.46,140.335 ; v4(109.095,140.97) F3.2@108.46,140.335
  other v2: 111.265,144.565 108.865,145.365
BANK35_VCC: C12.1 C13.1 C14.1 C15.1 C16.1 C17.1 C39.1 C40.1 C41.1 C249.2 F1.2 F4.2 F7.2 J2.42 J2.43 J3.42 J3.43 R3.1 R16.2 R18.1 R28.2 R29.2 R105.1 U1.A13 U1.B16 U1.C19 U1.D12 U1.E15 U1.F18 U1.H14 U1.J17 U1.K20 U1.M16 U12.32 U17.1 | length 52.5
  Top Layer w0.152: U1.J17@114.865,146.565 v2(115.265,146.165) ; U1.B16@120.465,147.365 v2(120.865,146.965)
  Top Layer w0.254: v4(112.065,146.965) U1.M16@112.465,147.365 ; U1.K20@114.065,144.165 v2(114.465,143.765) ; U1.H14@115.665,148.965 v2(116.065,148.565) ; U1.F18@117.265,145.765 v2(117.665,145.365) ; U1.E15@118.065,148.165 v2(118.465,147.765) ; U1.D12@118.865,150.565 v2(119.265,150.165) ; U1.C19@119.665,144.965 v2(120.065,144.565) ; U1.A13@121.265,149.765 v2(121.665,149.365) ; v3(127.292,137.684) 127.838,138.23 127.838,139.04 128.768,139.97 128.768,141.092 U12.32@128.75,141.11 ; F7.2@129.03,147.955 130.103,149.028 v3(130.213,149.028) ; J3.42@135.9,160.219 134.678,160.219 134.424,160.473 134.67,160.719 J3.43@135.9,160.719
  GND02 w0.109: v1(114.065,143.365) v2(114.465,143.765) ; v1(114.865,145.765) v2(115.265,146.165) ; v1(115.665,148.165) v2(116.065,148.565) ; v1(117.265,144.965) v2(117.665,145.365) ; v1(118.065,147.365) v2(118.465,147.765) ; v1(118.865,149.765) v2(119.265,150.165) ; v1(119.665,144.165) v2(120.065,144.565) ; v1(120.465,146.565) v2(120.865,146.965) ; v1(121.265,148.965) v2(121.665,149.365)
  GND02 w0.254: v1(111.665,146.565) v4(112.065,146.965)
  ART07 w0.178: v1(111.665,146.565) 112.059,146.171 114.215,146.171 114.622,145.765 v1(114.865,145.765)
  PWR13 w0.254: v1(111.665,146.565) v4(112.065,146.965)
  Bottom Layer w0.254: C13.1@111.748,147.765 111.748,147.282 v4(112.065,146.965) 111.835,146.735 C41.1@111.835,146.325 111.835,144.172 112.624,143.383 v4(113.335,143.383) 113.843,143.891 C14.1@114.652,143.891 ; C40.1@115.119,146.753 115.119,146.311 v2(115.265,146.165) 115.123,146.023 C12.1@115.123,145.507 ; C39.1@115.939,147.769 115.939,148.197 116.065,148.323 v2(116.065,148.565) ; v4(116.865,143.765) 117.135,143.495 U17.1@117.745,143.495 ; v4(116.865,146.165) 116.865,146.518 C15.1@117.1,146.753 ; C17.1@117.91,147.769 118.461,147.769 v2(118.465,147.765) ; v4(118.465,152.565) 118.592,152.692 R16.2@119.097,152.692 119.097,152.583 119.917,151.763 R105.1@119.917,151.579 ; C16.1@119.956,147.769 120.061,147.769 v2(120.865,146.965) ; v4(121.031,137.287) 121.676,137.287 C249.2@122.085,137.696 ; R3.1@127,138.655 127,137.976 v3(127.292,137.684) ; J2.42@136.1,160.219 134.802,160.219 v10(134.548,160.473) 134.794,160.719 J2.43@136.1,160.719
  Bottom Layer w0.381: v3(117.816,140.709) 117.949,140.843 R28.2@118.589,140.843 R29.2@118.589,139.7 ; R18.1@120.875,139.7 120.648,139.473 F4.2@120.648,138.049 ; F4.2@120.648,138.049 120.269,137.67 v4(120.269,137.287) 120.269,136.777 F1.2@120.648,136.398 121.031,136.781 v4(121.031,137.287) 121.031,137.666 F4.2@120.648,138.049
  other v2: 112.065,146.965
  other v4: 115.265,146.165 120.865,146.965 118.465,147.765 116.065,148.565
EN_1V0: R6.1 U10.27 | length 2.1
  Top Layer w0.254: U10.27@116.935,135.93 117.587,135.93 v3(117.831,135.687)
  Bottom Layer w0.254: R6.1@117.034,134.931 117.075,134.931 v3(117.831,135.687)
EN_1V5: U11.12 U16.2 U19.12 | length 8.7
  Top Layer w0.254: U19.12@127.885,155.345 v3(127.885,156.766)
  ART07 w0.254: v3(125.514,153.092) 125.514,153.835 127.885,156.206 v3(127.885,156.766)
  Bottom Layer w0.254: v3(125.514,153.092) 125.73,152.876 U16.2@125.73,152.13 ; v3(127.885,156.766) U11.12@127.885,158.345
EN_1V8: U14.12 U15.2 | length 12.8
  Top Layer w0.254: U14.12@100.735,144.53 102.016,144.53 102.902,143.644 v6(102.902,143.619)
  ART03 w0.254: v6@102.889,143.605 102.889,142.132 102.362,141.605 102.362,139.903 102.692,139.573 104.616,139.573 v3(105.194,138.995)
  Bottom Layer w0.381: v3(105.194,138.995) 106.045,138.144 U15.2@106.045,136.255
ETHPHY-1V0A: C26.2 C27.2 F9.2 U2.3 U2.8 U2.38 | length 30.7
  Top Layer w0.254: F9.2@126.674,150.044 v3(127.216,150.044)
  ART07 w0.381: v3(127.216,150.044) 127.883,150.044 128.346,149.581 130.556,149.581
  ART07 w0.508: v3(130.213,139.122) 130.537,139.122 130.861,139.446 130.861,149.276 130.556,149.581
  ART08 w0.381: v3(127.216,150.044) 127.216,149.231 v3(127.419,149.028)
  PWR13 w0.254: v3(127.419,149.028) 127.419,148.679 128.702,147.396 128.702,147.091 128.276,146.666 v4(128,146.666) ; v8(130.188,144.51) 129.905,144.51 129.692,144.297 129.692,142.723 129.905,142.51 v8(130.213,142.51) 130.54,142.51 130.81,142.24 130.81,139.268 130.664,139.122 v3(130.213,139.122)
  Bottom Layer w0.178: U2.38@128,146.01 v4(128,146.666) ; U2.8@129.5,142.51 v8(130.213,142.51) ; U2.3@129.5,144.51 v8(130.188,144.51)
  Bottom Layer w0.254: v4(128,146.666) 128,147.046 C26.2@128.473,147.52 ; C27.2@129.451,139.475 129.804,139.122 v3(130.213,139.122)
ETHPHY_3V3A: C29.2 F8.2 U2.11 | length 4.7
  Top Layer w0.254: F8.2@128.88,138.504 129.4,139.025 v3(129.4,140.392)
  Bottom Layer w0.178: U2.11@128.8,141.01 129.144,141.01 129.4,140.754 v3(129.4,140.392)
  Bottom Layer w0.254: C29.2@128.27,139.475 129.187,140.392 v3(129.4,140.392)
FPGA-STA0: J2.95 J3.95 R39.2 S0.2 U1.M14 | length 51.4
  Top Layer w0.114: v3(117.816,141.884) 117.816,141.616 S0.2@118.589,140.843 ; J3.95@131.9,161.719 133.043,161.719 v3(133.248,161.925)
  Top Layer w0.254: v2(112.065,148.565) U1.M14@112.465,148.965
  ART10 w0.099: v1(111.665,148.165) 111.398,148.165 111.277,148.285 111.277,149.987 111.507,150.217 111.507,150.838 112.203,151.534 118.336,151.534 118.72,151.917 118.72,152.451 118.491,152.679 118.491,153.187 118.694,153.391 119.101,153.391 119.253,153.543 119.253,153.949 119.456,154.153 122.352,154.153 122.582,153.923 123.012,153.923 123.215,154.126 123.215,154.572 124.132,155.489 124.132,156.325 126.327,158.519 128.267,158.519 128.702,158.953 128.702,160.259 130.01,161.567 131.064,161.567 131.194,161.696 133.02,161.696 v3(133.248,161.925)
  GND02 w0.109: v1(111.665,148.165) v2(112.065,148.565)
  ART07 w0.107: v1(111.665,148.165) 111.665,147.936 111.252,147.523 111.252,147.168 111.455,146.964 114.249,146.964 114.452,146.761 114.452,146.406 114.681,146.177 117.5,146.177 117.678,145.999 117.678,143.993 118.186,143.485 118.186,142.254 v3(117.816,141.884)
  Bottom Layer w0.089: J2.95@131.7,161.719 133.043,161.719 v3(133.248,161.925) ; v3@133.284,161.889 R39.2@133.883,161.889
FPGA-STA1: J2.94 J3.94 R39.1 S1.2 U1.M15 | length 51.6
  Top Layer w0.089: v2(112.065,147.765) U1.M15@112.465,148.165
  Top Layer w0.114: v3(117.816,140.043) 118.159,139.7 S1.2@118.589,139.7 ; J3.94@131.9,161.219 v3(133.248,161.219)
  ART10 w0.099: v1(111.665,147.365) v2(112.065,147.765) 112.065,149.987 111.784,150.268 111.784,150.724 112.318,151.257 118.451,151.257 118.996,151.803 118.996,152.561 119.253,152.818 119.253,153.111 119.532,153.391 122.326,153.391 122.582,153.646 123.127,153.646 123.492,154.011 123.492,154.457 124.409,155.374 124.409,156.21 126.441,158.242 128.382,158.242 128.979,158.839 128.979,160.144 130.124,161.29 131.179,161.29 131.308,161.42 133.048,161.42 v3(133.248,161.219)
  GND02 w0.109: v1(111.665,147.365) v2(112.065,147.765)
  ART07 w0.102: v3(117.816,140.043) 118.186,140.413
  ART07 w0.107: v1(111.665,147.365) 112.052,147.752 113.97,147.752 114.732,146.99 118.212,146.99 118.466,146.736 118.466,141.529 118.184,141.247 118.184,140.415 118.186,140.413
  Bottom Layer w0.089: J2.94@131.7,161.219 v3(133.248,161.219) ; v3@133.279,161.249 R39.1@133.883,161.249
